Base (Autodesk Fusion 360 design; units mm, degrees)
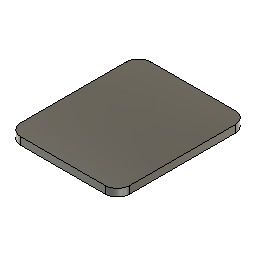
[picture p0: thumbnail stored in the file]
parameter "Lenght_Y" = 21 (= "21 mm * Ratio")
parameter "Lenght_X" = 17.6 (= "17.6 mm * Ratio")
parameter "Fillet" = 2
parameter "Lenght_Z" = 1.2
sketch "Sketch1" plane through (0, 0, 0) normal (0, 0, 1) x axis (1, 0, 0)
  line L1 (-15.6, 0) -> (-2, 0)
  line L2 (-17.6, 19) -> (-17.6, 2)
  line L3 (-2, 21) -> (-15.6, 21)
  line L4 (0, 2) -> (0, 19)
  arc A1 centre (-15.6, 19) radius 2 clockwise from (-17.6, 19) to (-15.6, 21)
  arc A2 centre (-2, 19) radius 2 clockwise from (-2, 21) to (0, 19)
  arc A3 centre (-2, 2) radius 2 clockwise from (0, 2) to (-2, 0)
  arc A4 centre (-15.6, 2) radius 2 clockwise from (-15.6, 0) to (-17.6, 2)
  point P1 (0, 0)
  point P2 (0, 0)
  point P3 (-17.6, 21)
  point P4 (0, 21)
  horizontal L1
  vertical L2
  horizontal L3
  vertical L4
  coincident P1 P2
  coincident P3 L2
  coincident P3 L3
  tangent L2 A1
  tangent L3 A1
  coincident P4 L3
  coincident P4 L4
  tangent L3 A2
  tangent L4 A2
  equal A1 A2
  coincident P2 L1
  coincident P2 L4
  tangent L1 A3
  tangent L4 A3
  equal A1 A3
  tangent L1 A4
  tangent L2 A4
  equal A1 A4
  dimension "d4" distance P3 P4 = 17.6 (= "Lenght_X")
  dimension "d5" distance P2 P4 = 21 (= "Lenght_Y")
  dimension "d7" radius A1 = 2 (= "Fillet")
extrude "Extrude1" new body sketch "Sketch1" along normal blind 1.2 (= "Lenght_Z")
